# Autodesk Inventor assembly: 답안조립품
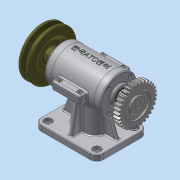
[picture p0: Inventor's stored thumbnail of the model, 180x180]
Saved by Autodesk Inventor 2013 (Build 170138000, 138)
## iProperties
Created: 2015-09
Part Number: 답안조립품
Document SubType Name: Assembly
Designer: dgall
Mass: 2246.61 g
Surface Area: 1628.2 cm^2
Volume: 528.248 cm^3
Density: 4.25295 g/cm^3
Author: dgall
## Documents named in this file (17)
- C:\Users\dgall\Desktop\350907V1036\답안조립품.iam
- C:\Users\dgall\Desktop\350907V1036\본체.ipt
- C:\Users\dgall\Desktop\350907V1036\본체 커버.ipt
- C:\Users\dgall\Desktop\350907V1036\앞커버.ipt
- C:\Users\dgall\Desktop\350907V1036\뒤커버.ipt
- C:\Users\dgall\Desktop\350907V1036\편심축.ipt
- C:\Users\dgall\Desktop\350907V1036\V-벨트풀리.ipt
- C:\Users\dgall\Desktop\350907V1036\슬라이드.ipt
- C:\Users\dgall\Desktop\350907V1036\스퍼기어.ipt
- C:\Users\dgall\Desktop\350907V1036\베어링 6202.ipt
- C:\Users\dgall\Desktop\350907V1036\베어링 6201.ipt
- C:\Users\dgall\Desktop\350907V1036\오일실.ipt
- C:\Users\dgall\Desktop\350907V1036\M4x0.5x14.ipt
- C:\Users\dgall\Desktop\350907V1036\M3x0.5x8.ipt
- C:\Users\dgall\Desktop\350907V1036\멈춤나사.ipt
- C:\Users\dgall\Desktop\350907V1036\키4x4.ipt
- C:\Users\dgall\Desktop\350907V1036\가변스프링.ipt
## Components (14 placed, 4 different names)
1. V-벨트풀리:1 — 각도:1
2. M4x0.5x14:1
3. M4x0.5x14:2
4. M4x0.5x14:3
5. M4x0.5x14:4
6. M3x0.5x8:1
7. M3x0.5x8:2
8. M3x0.5x8:3
9. M3x0.5x8:4
10. M3x0.5x8:5
11. M3x0.5x8:6
12. M3x0.5x8:7
13. M3x0.5x8:8
14. 가변스프링:1
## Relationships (1: Angle 1)
- 각도:1 [Angle]: V-벨트풀리:1
